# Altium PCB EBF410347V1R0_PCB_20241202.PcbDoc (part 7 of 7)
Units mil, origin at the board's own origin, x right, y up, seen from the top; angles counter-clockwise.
Board outline 5098.43 x 3464.57 mil, 6 copper layers (TOP, GND02, ART03, ART04, PWR05, BOTTOM), stack 47.2 mil thick; 566 components, 452 nets, 1905 pads, 1432 vias.
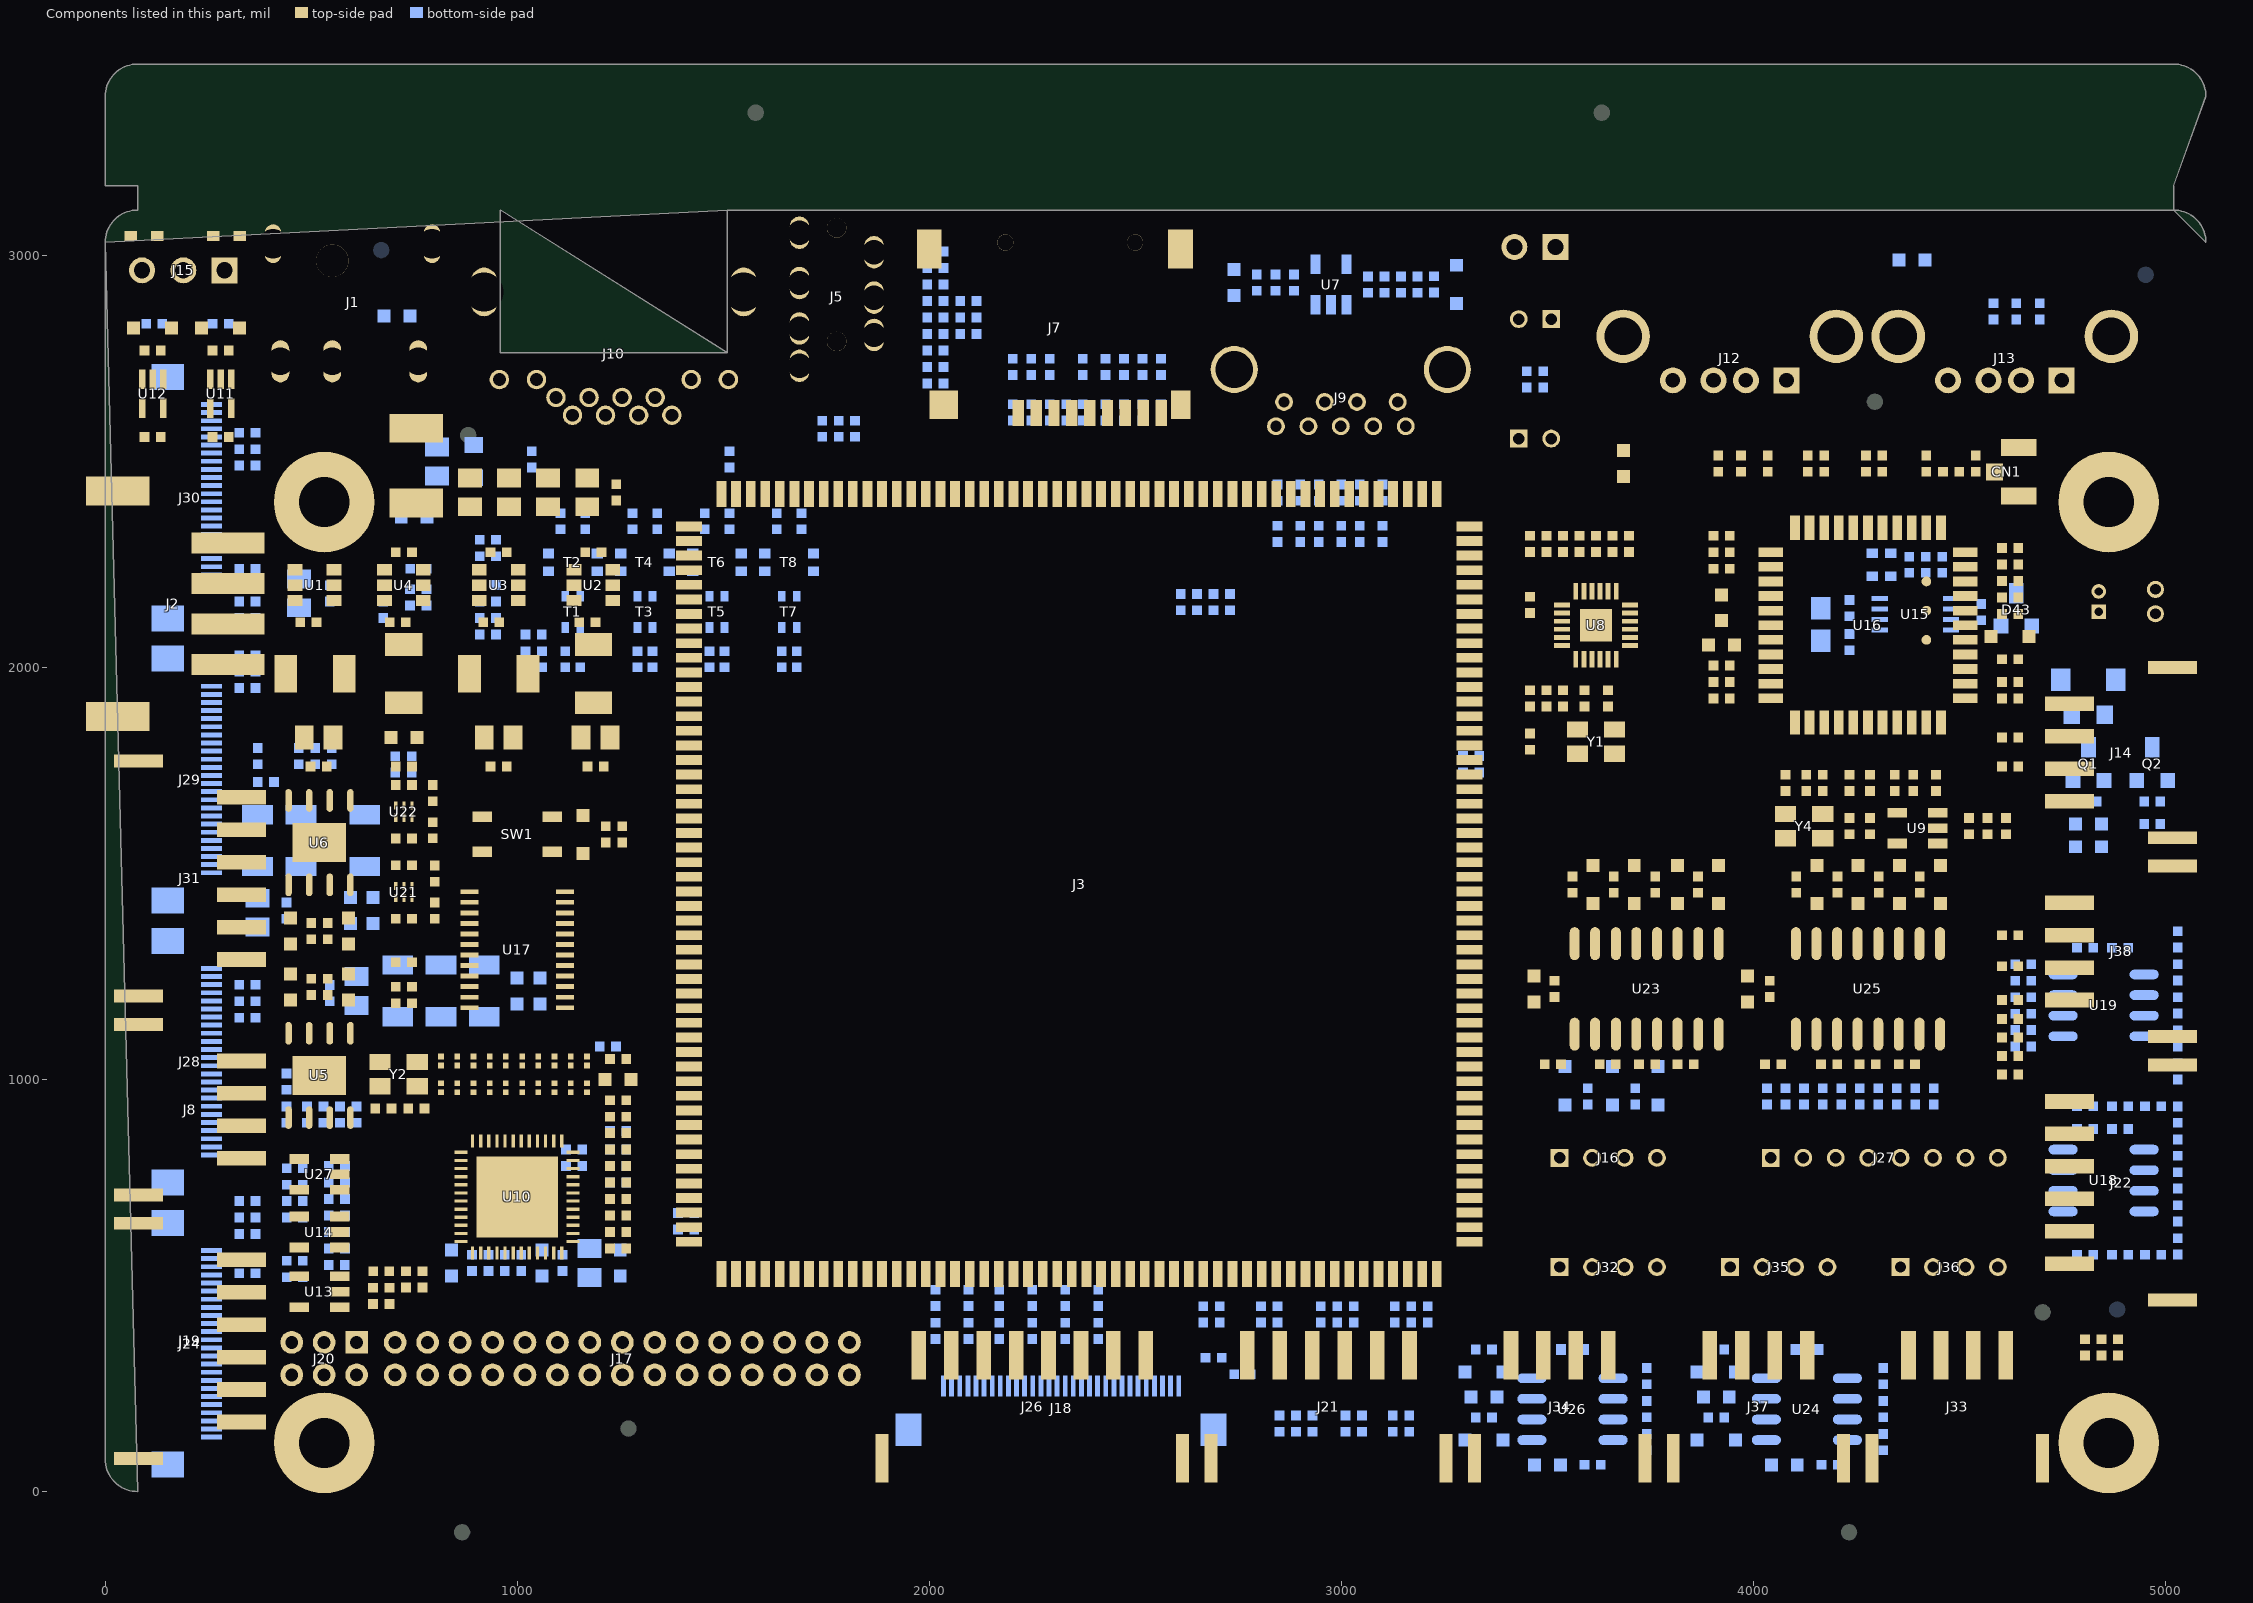
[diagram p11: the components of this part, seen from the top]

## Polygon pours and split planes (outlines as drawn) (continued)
VDD_LCD_3V3 on BOTTOM "BOTTOM-VDD_LCD_3V3 1" (solid, pour order 26): 2533,337 2520,324 2520,230 2552,230 2552,292 2552,304 2561,313 2677,313 2682,313 2682,337 2677,337 2533,337
VDD_LCD_5V on BOTTOM "BOTTOM-VDD_LCD_5V" (solid, pour order 40): 34 vertices, not listed, extent 2560,231 2752,297
VDD_5V on BOTTOM "BOTTOM-VDD_5V" (solid, pour order 56): 30 vertices, not listed, extent 353,1118 663,1394
12V on BOTTOM "BOTTOM-12V 1" (solid, pour order 22): 1234,603 1300,603 1307,596 1307,506 1302,501 1290,501 1284,507 1284,564 1277,571 1269,571 1234,571 1234,603
VDD_3V3 on BOTTOM "BOTTOM-VDD_3V3" (solid, pour order 6): 82 vertices, not listed, extent 2917,173 2943,268
12V on BOTTOM "BOTTOM-12V 2" (solid, pour order 2): 82 vertices, not listed, extent 1000,1345 1062,1368
VDD_5V on BOTTOM "BOTTOM-VDD_5V 1" (solid, pour order 17): 353,693 353,730 358,735 411,735 418,728 418,674 412,668 399,668 393,674 393,687 387,693 353,693
12V on BOTTOM "BOTTOM-12V 3" (solid, pour order 44): 23 vertices, not listed, extent 441,2188 652,2290
VDD_CAM1_5V on BOTTOM "BOTTOM-VDD_CAM1_5V" (solid, pour order 32): 232,1276 329,1276 337,1268 337,1138 314,1138 314,1219 308,1225 232,1225 232,1276
VCCA_1V8 on BOTTOM "BOTTOM-VCCA_1V8" (solid, pour order 1): 82 vertices, not listed, extent 2476,400 2498,461
VDD_3V3 on BOTTOM "BOTTOM-VDD_3V3 1" (solid, pour order 16): 570,762 570,698 623,698 628,703 628,742 621,749 598,749 594,753 594,762 593,762 570,762
N16783471 on BOTTOM "BOTTOM-N16783471" (solid, pour order 61): 666,1426 666,1540 333,1540 333,1425 341,1417 346,1412 498,1412 507,1421 507,1478 513,1484 516,1484 572,1484 580,1476 580,1426 666,1426
VDD_LVDS on BOTTOM "BOTTOM-VDD_LVDS" (solid, pour order 23): 468,797 468,693 517,693 523,699 523,746 516,753 498,753 491,760 491,797 468,797
VCCA_1V8 on BOTTOM "BOTTOM-VCCA_1V8 1" (solid, pour order 3): 82 vertices, not listed, extent 2552,662 2576,727
LVDS_5V on BOTTOM "BOTTOM-LVDS_5V" (solid, pour order 14): 1076,508 1076,542 1071,547 958,547 958,524 1038,524 1044,518 1044,508 1076,508
LVDS_12V on BOTTOM "BOTTOM-LVDS_12V" (solid, pour order 29): 1098,547 1259,547 1266,540 1266,502 1261,497 1146,497 1146,519 1141,524 1098,524 1098,547
N16724119 on TOP "TOP-N16724119" (solid, pour order 10): 82 vertices, not listed, extent 890,2099 932,2177
GND on TOP "TOP-GND" (solid, pour order 82): 86 vertices, not listed, extent 20,20 5078.42,3090.24
N16723587 on TOP "TOP-N16723587" (solid, pour order 15): 82 vertices, not listed, extent 443,2098 485,2177
N16722109 on TOP "TOP-N16722109" (solid, pour order 41): 19 vertices, not listed, extent 1140,2028 1250,2214
VCC5V0_USB on TOP "TOP-VCC5V0_USB" (solid, pour order 54): 912,1867 912,2030 847,2030 841,2024 841,1758 851,1748 947,1748 947,1846 947,1859 920,1859 912,1867
N16723611 on TOP "TOP-N16723611" (solid, pour order 48): 18 vertices, not listed, extent 497,1940 606,2214
VCCA_1V8 on TOP "TOP-VCCA_1V8" (solid, pour order 7): 3342,827 3254,827 3248,821 3248,771 3253,766 3262,766 3272,776 3272,804 3279,811 3342,811 3342,827
LVDS_12V on TOP "TOP-LVDS_12V" (solid, pour order 52): 82 vertices, not listed, extent 204,1274 390,1389
VCC5V0_USB on TOP "TOP-VCC5V0_USB 1" (solid, pour order 25): 82 vertices, not listed, extent 4303.11,1555 4403.11,1615
N16723079 on TOP "TOP-N16723079" (solid, pour order 12): 82 vertices, not listed, extent 660,2099 702,2177
N16722097 on TOP "TOP-N16722097" (solid, pour order 11): 82 vertices, not listed, extent 1120,2099 1162,2177
VDD_3V3 on TOP "TOP-VDD_3V3" (solid, pour order 36): 21 vertices, not listed, extent 679,1173 757,1402
12V on TOP "TOP-12V" (solid, pour order 62): 40 vertices, not listed, extent 690,2223 1253,2436
VDD_5V on TOP "TOP-VDD_5V" (solid, pour order 21): 82 vertices, not listed, extent 434,436 497,497
VDD_3V3 on TOP "TOP-VDD_3V3 1" (solid, pour order 51): 20 vertices, not listed, extent 623,1748 770,1942
VCCA_1V8 on TOP "TOP-VCCA_1V8 1" (solid, pour order 35): 2508,273 2508,390 2500,398 2486,398 2477,407 2477,453 2483,459 2538,459 2544,453 2544,273 2508,273
VCC3V3_WIFI on TOP "TOP-VCC3V3_WIFI" (solid, pour order 46): 4071.11,1938 3989.11,1938 3982.11,1945 3982.11,2121 3973.11,2130 3907.11,2130 3907.11,2098 3924.11,2098 3931.11,2091 3931.11,2017 3931.11,1913 4071.11,1913 4071.11,1938
12V_IN on TOP "TOP-12V_IN" (solid, pour order 66): 34 vertices, not listed, extent 116,1982 820,2873
VCC5V0_USB20_HUB on TOP "TOP-VCC5V0_USB20_HUB" (solid, pour order 8): 4065,2565 4085,2565 4092,2558 4092,2509 4086,2503 4023,2503 4023,2526 4053,2526 4059,2532 4059,2559 4065,2565
VDD_3V3 on TOP "TOP-VDD_3V3 2" (solid, pour order 27): 82 vertices, not listed, extent 2912,204 2948,390
VCC5V0_SYS on TOP "TOP-VCC5V0_SYS" (solid, pour order 55): 17 vertices, not listed, extent 1075,1709 1230,1942
VDD_LCD_3V3 on TOP "TOP-VDD_LCD_3V3" (solid, pour order 13): 546,605 595,605 602,612 602,636 607,641 621,641 628,634 628,582 623,577 549,577 546,580 546,605
VDD_5V on TOP "TOP-VDD_5V 1" (solid, pour order 19): 82 vertices, not listed, extent 4873,283 4936,342
VDD_LVDS on TOP "TOP-VDD_LVDS" (solid, pour order 34): 20 vertices, not listed, extent 678,523 915,630
N16724131 on TOP "TOP-N16724131" (solid, pour order 49): 21 vertices, not listed, extent 944,1940 1054,2214
12V on TOP "TOP-12V 1" (solid, pour order 28): 25 vertices, not listed, extent 507,2188 648,2287
VDD_3V3 on TOP "TOP-VDD_3V3 3" (solid, pour order 50): 245,675 301,675 312,664 312,615 322,605 494,605 494,581 455,581 427,553 419,545 390,545 249,545 236,558 236,666 245,675
VDD_IO on TOP "TOP-VDD_IO" (solid, pour order 43): 4827,571 4827,389 4834,382 4897,382 4897,358 4793,358 4793,523 4781,535 4708,535 4708,571 4827,571
N16722987 on TOP "TOP-N16722987" (solid, pour order 39): 20 vertices, not listed, extent 680,2028 790,2214
VDD_3V3 on TOP "TOP-VDD_3V3 4" (solid, pour order 20): 82 vertices, not listed, extent 3891.11,2161 3956.11,2220
VCC5V0_USB20_HUB on TOP "TOP-VCC5V0_USB20_HUB 1" (solid, pour order 57): 4424.11,1585 4502.11,1585 4511.11,1594 4511.11,1607 4698.11,1607 4709.11,1618 4709.11,1694 4826.11,1694 4826.11,1571 4816.11,1561 4424.11,1561 4424.11,1585
VDD_LCD_5V on TOP "TOP-VDD_LCD_5V" (solid, pour order 47): 27 vertices, not listed, extent 546,197 747,468
VDD_5V on TOP "TOP-VDD_5V 2" (solid, pour order 58): 24 vertices, not listed, extent 224,669 423,1183
VCC3V3_WIFI on TOP "TOP-VCC3V3_WIFI 1" (solid, pour order 0): 80 vertices, not listed, extent 3985,2395 4050,2415
VDDIO_LVDS on TOP "TOP-VDDIO_LVDS" (solid, pour order 4): 1104,867 1138,867 1153,882 1165,882 1172,875 1172,864 1143,835 1104,835 1104,867
VDD_5V on TOP "TOP-VDD_5V 3" (solid, pour order 53): 18 vertices, not listed, extent 383,1748 507,2030
VCC5V0_SYS on TOP "TOP-VCC5V0_SYS 1" (solid, pour order 38): 69 vertices, not listed, extent 3252,554 3372,653
VCC5V0_USB20_HUB on TOP "TOP-VCC5V0_USB20_HUB 2" (solid, pour order 45): 17 vertices, not listed, extent 4525,1175 4826.11,1250
VDD_3V3 on TOP "TOP-VDD_3V3 5" (solid, pour order 9): 4833,343 4833,317 4825,309 4796,309 4792,305 4792,281 4795,278 4854,278 4857,281 4857,343 4833,343
VCCIO_ACODEC on ART04 "ART04-VCCIO_ACODEC" (solid, pour order 63): 30 vertices, not listed, extent 2707,886 3315,2546
VDD_LCD_3V3 on ART04 "ART04-VDD_LCD_3V3" (solid, pour order 68): 42 vertices, not listed, extent 562,211 2671,643
VCC5V0_USB20_HUB on ART04 "ART04-VCC5V0_USB20_HUB" (solid, pour order 72): 37 vertices, not listed, extent 4068,1197 4836,2862
no net on ART04 "ART04-No Net" (solid, pour order 75): 45 vertices, not listed, extent 844,1456.5 4439,3035
GND on ART04 "ART04-GND" (solid, pour order 76): 18 vertices, not listed, extent 1509,667 2963,2274
VDD_5V on ART04 "ART04-VDD_5V" (solid, pour order 74): 93 vertices, not listed, extent 275,91 5016,2295
VDD_5V on ART04 "ART04-VDD_5V 1" (solid, pour order 59): 364,733 448,733 465,716 465,537 474,528 496,528 505,519 506,519 506,473 496,463 359,463 352,470 352,721 364,733
VCCA_1V8 on ART04 "ART04-VCCA_1V8" (solid, pour order 71): 36 vertices, not listed, extent 2554,370 4104,1436
GND on ART04 "ART04-GND 1" (solid, pour order 70): 36 vertices, not listed, extent 4121,366 4798,1765
VCC5V0_SYS on ART04 "ART04-VCC5V0_SYS" (solid, pour order 77): 47 vertices, not listed, extent 1072,498.5 3856,2825
LVDS_12V on ART04 "ART04-LVDS_12V" (solid, pour order 64): 242,461 242,1378 228,1392 115,1392 101,1378 101,340 124,317 662,317 675,330 675,409 675,433 665,443 260,443 242,461
12V on ART04 "ART04-12V" (solid, pour order 73): 84 vertices, not listed, extent 500,214 4904,2348
GND on ART04 "ART04-GND 2" (solid, pour order 78): 102 vertices, not listed, extent 20,20 5078.42,3090.24
VCC3V3_SD on ART04 "ART04-VCC3V3_SD" (solid, pour order 67): 31 vertices, not listed, extent 2609,841 3314,2546
VCC3V3_WIFI on ART04 "ART04-VCC3V3_WIFI" (solid, pour order 69): 25 vertices, not listed, extent 3732,1785 4686,2478
VDD_LCD_5V on ART04 "ART04-VDD_LCD_5V" (solid, pour order 65): 25 vertices, not listed, extent 684,73 2671,296
GND on GND02 "GND02-GND" (solid, pour order 83): 86 vertices, not listed, extent 20,20 5078.42,3090.24
VDD_3V3 on PWR05 "PWR05-VDD_3V3" (solid, pour order 80): 86 vertices, not listed, extent 20,20 5078.42,3090.24
GND on ART03 "ART03-GND" (solid, pour order 81): 86 vertices, not listed, extent 20,20 5078.42,3090.24

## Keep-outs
Multi-Layer:
  region: 4609.37,2510 4609.37,2440 4684.37,2440 4684.37,2510 4609.37,2510

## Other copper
TOP:
  drawing of 457 lines, arcs and shapes, not listed
GND02:
  drawing of 732 lines, arcs and shapes, not listed
ART03:
  drawing of 126 lines, arcs and shapes, not listed
ART04:
  drawing of 836 lines, arcs and shapes, not listed
PWR05:
  drawing of 1426 lines, arcs and shapes, not listed
BOTTOM:
  drawing of 423 lines, arcs and shapes, not listed

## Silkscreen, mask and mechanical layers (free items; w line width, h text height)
Top Overlay:
  text "ID" at 1643.74,3264.46 h50 r180
  text "ID" at 3697.28,3264.46 h50 r180
  text "ID" at 4230,2727 h50
  text "ID" at 816,2646 h50
  text "ID" at 4637,517 h50
  text "ID" at 1205,235 h50
  text "ID" at 801.14,-16.74 h50
  text "ID" at 4167.28,-16.74 h50
Bottom Overlay:
  text "ID" at 1643.74,3428.46 h50
  text "ID" at 3697.28,3428.46 h50
  text "ID" at 735,3095 h50
  text "ID" at 5017,3035 h50
  text "ID" at 4948,524 h50
  text "ID" at 931.14,-16.74 h50
  text "ID" at 4297.28,-16.74 h50
OUTLINE:
  lines w1: 78.74,0 cw(c78.74,78.74) 0,78.74 ; 5098.43,3031.5 ccw(c5019.69,3031.5) 5019.69,3110.24 ; 0,78.74 0,3031.5 ; 0,78.74 0,3031.5 ; 0,3031.5 cw(c78.74,3031.5) 78.74,3110.24 ; 78.74,3110.24 958.93,3110.24 958.93,2763.78 ; 78.74,3110.24 78.74,3169.29 0,3169.29 0,3385.83 cw(c78.74,3385.83) 78.74,3464.57 5019.69,3464.57 cw(c5019.69,3385.83) 5098.43,3385.83 5098.43,3169.29 5019.69,3169.29 5019.69,3110.24 ; 958.93,2763.78 1510.11,2763.78 ; 958.93,2763.78 1510.11,2763.78 ; 1510.11,2763.78 1510.11,3110.24 ; 1510.11,2763.78 1510.11,3110.24 ; 1510.11,3110.24 5019.69,3110.24
PLACE_BOUND_TOP:
  region: 826.14,-138.74 906.14,-138.74 906.14,-58.74 826.14,-58.74
  region: 4192.28,-138.74 4272.28,-138.74 4272.28,-58.74 4192.28,-58.74
  region: 3672.28,3386.46 3592.28,3386.46 3592.28,3306.46 3672.28,3306.46 3672.28,3386.46
  region: 1618.74,3386.46 1538.74,3386.46 1538.74,3306.46 1618.74,3306.46 1618.74,3386.46
  region: 4662,395 4742,395 4742,475 4662,475
  region: 841,2524 921,2524 921,2604 841,2604
  region: 4255,2605 4335,2605 4335,2685 4255,2685
  region: 1230,113 1310,113 1310,193 1230,193
PLACE_BOUND_BOTTOM:
  region: 906.14,-138.74 906.14,-58.74 826.14,-58.74 826.14,-138.74 906.14,-138.74
  region: 4272.28,-138.74 4272.28,-58.74 4192.28,-58.74 4192.28,-138.74 4272.28,-138.74
  region: 3672.28,3306.46 3672.28,3386.46 3592.28,3386.46 3592.28,3306.46 3672.28,3306.46
  region: 1618.74,3306.46 1618.74,3386.46 1538.74,3386.46 1538.74,3306.46 1618.74,3306.46
  region: 4923,402 4923,482 4843,482 4843,402 4923,402
  region: 710,2973 710,3053 630,3053 630,2973 710,2973
  region: 4992,2913 4992,2993 4912,2993 4912,2913 4992,2913
NCLEGEND-1-6:
  circle w1: c6310.5,844 r45.28
  lines w1: 5861,-1281 10697,-1281 ; 5861,-1031 10697,-1031 ; 5861,-781 10697,-781 ; 5861,-531 10697,-531 ; 5861,-281 10697,-281 ; 5861,-31 10697,-31 ; 5861,219 10697,219 ; 5861,469 10697,469 ; 5861,719 10697,719 ; 5861,969 10697,969 ; 5861,1219 10697,1219 ; 5861,1469 10697,1469 ; 5861,1719 10697,1719 ; 5861,1969 10697,1969 ; 5861,2219 10697,2219 ; 5861,2469 10697,2469 ; 5861,2719 10697,2719 ; 5861,2969 10697,2969 ; 5861,3219 10697,3219 ; 5861,3469 10697,3469 ; 5861,3719 10697,3719 ; 6305.5,3094 6315.5,3094 ; 6310.5,3089 6310.5,3099 ; 6760,-1531 6760,3469 ; 8651,-1531 8651,3469 ; 9922,-1531 9922,3469 ; 5861,-1531 5861,3969 10697,3969 10697,-1531 5861,-1531 ; 6265.22,560.04 6265.22,627.96 6355.78,627.96 6355.78,560.04 6265.22,560.04 ; 6280.67,2344 6289.41,2322.91 6310.5,2314.17 6331.59,2322.91 6340.33,2344 6331.59,2365.09 6310.5,2373.83 6289.41,2365.09 6280.67,2344 ; 6280.97,1089.08 ccw(c6310.5,1089.08) 6340.03,1089.08 6340.03,1098.92 ccw(c6310.5,1098.92) 6280.97,1098.92 6280.97,1089.08 ; 6282.9,-1171.7 ccw(c6282.9,-1156) 6282.9,-1140.3 6338.1,-1140.3 ccw(c6338.1,-1156) 6338.1,-1171.7 6282.9,-1171.7 ; 6282.94,-1445.37 ccw(c6282.94,-1406) 6282.94,-1366.63 6338.06,-1366.63 ccw(c6338.06,-1406) 6338.06,-1445.37 6282.94,-1445.37 ; 6286.9,-925.7 ccw(c6286.9,-906) 6286.9,-886.3 6334.1,-886.3 ccw(c6334.1,-906) 6334.1,-925.7 6286.9,-925.7 ; 6294.75,1578.25 6310.5,1609.75 6326.25,1578.25 6294.75,1578.25 ; 6294.75,1844 6310.5,1859.75 6326.25,1844 6310.5,1828.25 6294.75,1844 ; 6295.74,-685.53 ccw(c6295.74,-656) 6295.74,-626.47 6325.26,-626.47 ccw(c6325.26,-656) 6325.26,-685.53 6295.74,-685.53 ; 6296.72,2087.11 6310.5,2080.22 6324.28,2087.11 6324.28,2100.89 6310.5,2107.78 6296.72,2100.89 6296.72,2087.11 ; 6297.7,2594 6304.1,2581.2 6316.9,2581.2 6323.3,2594 6316.9,2606.8 6304.1,2606.8 6297.7,2594 ; 6300.66,2834.16 6320.34,2834.16 6320.34,2853.84 6300.66,2853.84 6300.66,2834.16 ; 6306.07,1317.43 ccw(c6306.07,1344) 6306.07,1370.57 6314.93,1370.57 ccw(c6314.93,1344) 6314.93,1317.43 6306.07,1317.43
  text "DRILL CHART: TOP to BOTTOM" at 6979,3781.5 h125
  text "ALL UNITS ARE IN MILS" at 7229,3531.5 h125
  text "FIGURE" at 6010.5,3281.5 h125
  text "SIZE" at 7505.5,3281.5 h125
  text "PLATED" at 8986.5,3281.5 h125
  text "QTY" at 10159.5,3281.5 h125
  text "10.0" at 7505.5,3031.5 h125
  text "PLATED" at 8986.5,3031.5 h125
  text "1432" at 10109.5,3031.5 h125
  text "19.689" at 7405.5,2781.5 h125
  text "PLATED" at 8986.5,2781.5 h125
  text "2" at 10259.5,2781.5 h125
  text "25.591" at 7405.5,2531.5 h125
  text "PLATED" at 8986.5,2531.5 h125
  text "2" at 10259.5,2531.5 h125
  text "27.559" at 7405.5,2281.5 h125
  text "PLATED" at 8986.5,2281.5 h125
  text "9" at 10259.5,2281.5 h125
  text "27.559" at 7405.5,2031.5 h125
  text "PLATED" at 8986.5,2031.5 h125
  text "28" at 10209.5,2031.5 h125
  text "31.496" at 7405.5,1781.5 h125
  text "PLATED" at 8986.5,1781.5 h125
  text "12" at 10209.5,1781.5 h125
  text "31.5" at 7505.5,1531.5 h125
  text "PLATED" at 8986.5,1531.5 h125
  text "36" at 10209.5,1531.5 h125
  text "35.429" at 7405.5,1281.5 h125
  text "PLATED" at 8986.5,1281.5 h125
  text "8" at 10259.5,1281.5 h125
  text "39.37" at 7455.5,1031.5 h125
  text "PLATED" at 8986.5,1031.5 h125
  text "5" at 10259.5,1031.5 h125
  text "90.551" at 7405.5,781.5 h125
  text "PLATED" at 8986.5,781.5 h125
  text "2" at 10259.5,781.5 h125
  text "90.551" at 7405.5,531.5 h125
  text "PLATED" at 8986.5,531.5 h125
  text "4" at 10259.5,531.5 h125
  text "122.051" at 7355.5,281.5 h125
  text "PLATED" at 8986.5,281.5 h125
  text "4" at 10259.5,281.5 h125
  text "39.37" at 7455.5,31.5 h125
  text "NON-PLATED" at 8786.5,31.5 h125
  text "2" at 10259.5,31.5 h125
  text "47.24" at 7455.5,-218.5 h125
  text "NON-PLATED" at 8786.5,-218.5 h125
  text "2" at 10259.5,-218.5 h125
  text "78.701" at 7405.5,-468.5 h125
  text "NON-PLATED" at 8786.5,-468.5 h125
  text "1" at 10259.5,-468.5 h125
  text "59.059x29.531" at 7055.5,-718.5 h125
  text "PLATED" at 8986.5,-718.5 h125
  text "7" at 10259.5,-718.5 h125
  text "66.902x19.701" at 7055.5,-968.5 h125
  text "PLATED" at 8986.5,-968.5 h125
  text "3" at 10259.5,-968.5 h125
  text "70.902x15.701" at 7055.5,-1218.5 h125
  text "PLATED" at 8986.5,-1218.5 h125
  text "2" at 10259.5,-1218.5 h125
  text "94.488x39.37" at 7105.5,-1468.5 h125
  text "PLATED" at 8986.5,-1468.5 h125
  text "2" at 10259.5,-1468.5 h125
DRAWING_ORIGIN:
  lines w1: -25,0 25,0 ; 0,-25 0,25
PIN_NUMBER:
  text "1" at 1546.74,3346.46 h40 r180
  text "1" at 1546.74,3346.46 h40
  text "1" at 3600.28,3346.46 h40 r180
  text "1" at 3600.28,3346.46 h40
  text "1" at 638,3013 h40
  text "1" at 4920,2953 h40
  text "1" at 4263,2645 h40
  text "1" at 849,2564 h40
  text "1" at 4851,442 h40
  text "1" at 4670,435 h40
  text "1" at 1238,153 h40
  text "1" at 834.14,-98.74 h40
  text "1" at 834.14,-98.74 h40
  text "1" at 4200.28,-98.74 h40
  text "1" at 4200.28,-98.74 h40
